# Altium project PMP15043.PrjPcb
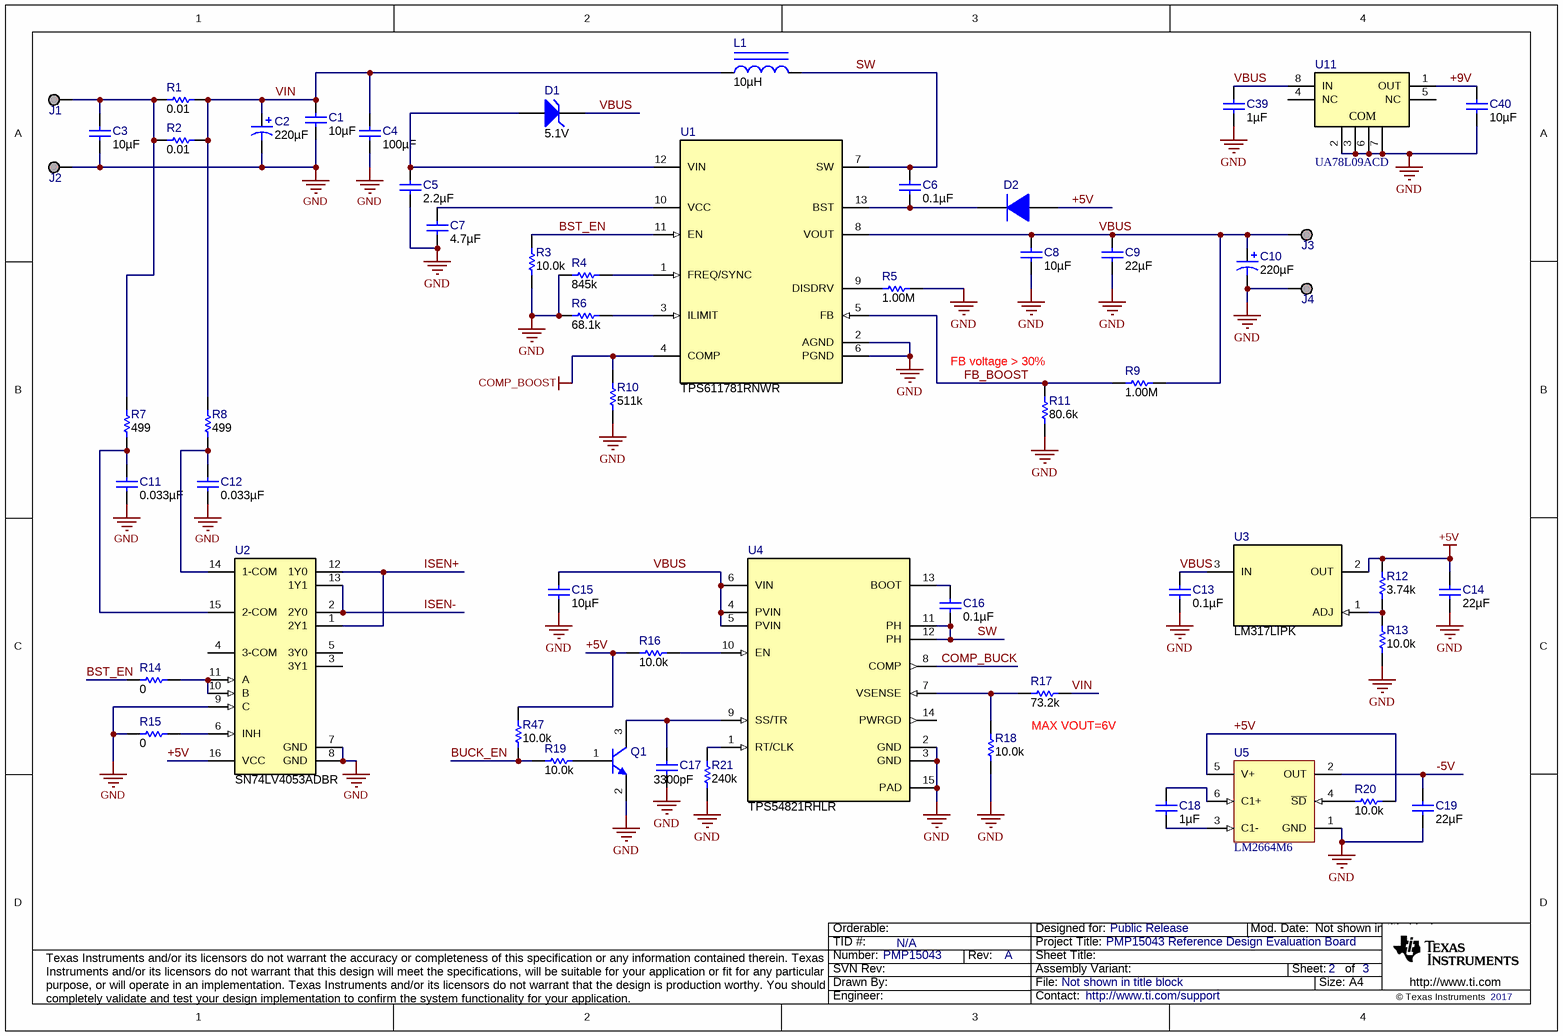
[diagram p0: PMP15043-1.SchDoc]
TID: N/A; TechSupport: http://www.ti.com/support; SCH_Rev: A; PRJ_Title: PMP15043 Reference Design Evaluation Board; PRJ_Number: PMP15043; PRJ_Customer: Public Release; PCB_Rev: A; CopyrightYear: 2017
2 sheets, 118 parts. Net scope: global (net labels, ports and power ports of the same name join across sheets).
Board file: PMP15043.PcbDoc
Sheets:
  PMP15043-1.SchDoc
  PMP15043-2.SchDoc

## Sheet PMP15043-1.SchDoc
size A4; Date: Not shown in title block; ApprovedBy: Not shown in title block; CheckedBy: Not shown in title block; Author: Not shown in title block; CompanyName: Not shown in title block; Engineer: Not shown in title block; Organization: Not shown in title block; Address1: Not shown in title block; Address2: Not shown in title block; Address3: Not shown in title block; Address4: Not shown in title block; DocumentNumber: 1; Revision: Use project parameter SCH_Rev; SheetNumber: 2; SheetTotal: 3; PageSetup: Record=PageOptions¦CenterHorizontal=True¦CenterVertical=True¦PrintScale=1.00¦XCorrection=1.00¦YCorrection=1.00¦PrintKind=0¦BorderSize=5000000¦LeftOffset=0¦BottomOffset=0¦Orientation=2¦PaperLength=1000¦PaperWidth=1000¦Scale=100¦PaperSource=15¦PrintQuality=600¦MediaType=1¦DitherType=10¦PaperKind=Letter¦PrintScaleMode=1

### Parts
C1  ValueDisplayed: 10µF  [0603]  (hidden comment: GRM188R61E106MA73D)
C2  ValueDisplayed: 220µF  [SM_RADIAL_G]  (hidden comment: EEE-FC1E221P)
C3  ValueDisplayed: 10µF  [0603]  (hidden comment: GRM188R61E106MA73D)
C4  ValueDisplayed: 100µF  [1210_270]  (hidden comment: GRM32ER61A107ME20L)
C5  ValueDisplayed: 2.2µF  [0402_070]  (hidden comment: GRM155R61E225KE11D)
C6  ValueDisplayed: 0.1µF  [0402]  (hidden comment: GRM155R61C104KA88D)
C7  ValueDisplayed: 4.7µF  [0402]  (hidden comment: GRM155R61A475MEAAD)
C8  ValueDisplayed: 10µF  [0603]  (hidden comment: GRM188R61E106MA73D)
C9  ValueDisplayed: 22µF  [1210_270]  (hidden comment: GRM32ER61E226KE15L)
C10  ValueDisplayed: 220µF  [SM_RADIAL_G]  (hidden comment: EEE-FC1E221P)
C11  ValueDisplayed: 0.033µF  [0402]  (hidden comment: GRM155R71A333KA01D)
C12  ValueDisplayed: 0.033µF  [0402]  (hidden comment: GRM155R71A333KA01D)
C13  ValueDisplayed: 0.1µF  [0402]  (hidden comment: GRM155R71E104KE14D)
C14  ValueDisplayed: 22µF  [0603]  (hidden comment: GRM188R61A226ME15D)
C15  ValueDisplayed: 10µF  [0603]  (hidden comment: GRM188R61E106MA73D)
C16  ValueDisplayed: 0.1µF  [0402]  (hidden comment: GRM155R61C104KA88D)
C17  ValueDisplayed: 3300pF  [0402]  (hidden comment: GRM155R71H332KA01D)
C18  ValueDisplayed: 1µF  [0603]  (hidden comment: GRM188R61A105KA61D)
C19  ValueDisplayed: 22µF  [0603]  (hidden comment: GRM188R61A226ME15D)
C39  ValueDisplayed: 1µF  [0603]  (hidden comment: GRM188R61E105KA12D)
C40  ValueDisplayed: 10µF  [0603]  (hidden comment: GRM188R61E106MA73D)
D1  value 5.1V  [SOD-323]  (hidden comment: BZT52C5V1S-7-F)
D2  1N4148X-TP  [SOD-523]  (value not drawn)
J1  Suggest using a net name here  [Keystone1502-2]  (value not drawn)
J2  Suggest using a net name here  [Keystone1502-2]  (value not drawn)
J3  Suggest using a net name here  [Keystone1502-2]  (value not drawn)
J4  Suggest using a net name here  [Keystone1502-2]  (value not drawn)
L1  ValueDisplayed: 10µH  [WE-HCC_1210]  (hidden comment: 7443321000)
Q1  MMBT3904-7-F  [SOT-23]  (value not drawn)
R1  ValueDisplayed: 0.01  [2010]  (hidden comment: CSRN2010FK10L0)
R2  ValueDisplayed: 0.01  [2010]  (hidden comment: CSRN2010FK10L0)
R3  ValueDisplayed: 10.0k  [0402]  (hidden comment: CRCW040210K0FKED)
R4  ValueDisplayed: 845k  [0402]  (hidden comment: CRCW0402845KFKED)
R5  ValueDisplayed: 1.00M  [0402]  (hidden comment: CRCW04021M00FKED)
R6  ValueDisplayed: 68.1k  [0402]  (hidden comment: CRCW040268K1FKED)
R7  ValueDisplayed: 499  [0603]  (hidden comment: CRCW0603499RFKEA)
R8  ValueDisplayed: 499  [0603]  (hidden comment: CRCW0603499RFKEA)
R9  ValueDisplayed: 1.00M  [0402]  (hidden comment: CRCW04021M00FKED)
R10  ValueDisplayed: 511k  [0402]  (hidden comment: CRCW0402511KFKED)
R11  ValueDisplayed: 80.6k  [0402]  (hidden comment: CRCW040280K6FKED)
R12  ValueDisplayed: 3.74k  [0402]  (hidden comment: CRCW04023K74FKED)
R13  ValueDisplayed: 10.0k  [0402]  (hidden comment: CRCW040210K0FKED)
R14  ValueDisplayed: 0  [0603]  (hidden comment: CRCW06030000Z0EA)
R15  ValueDisplayed: 0  [0603]  (hidden comment: CRCW06030000Z0EA)
R16  ValueDisplayed: 10.0k  [0402]  (hidden comment: CRCW040210K0FKED)
R17  ValueDisplayed: 73.2k  [0402]  (hidden comment: CRCW040273K2FKED)
R18  ValueDisplayed: 10.0k  [0402]  (hidden comment: CRCW040210K0FKED)
R19  ValueDisplayed: 10.0k  [0402]  (hidden comment: CRCW040210K0FKED)
R20  ValueDisplayed: 10.0k  [0402]  (hidden comment: CRCW040210K0FKED)
R21  ValueDisplayed: 240k  [0402]  (hidden comment: CRCW0402240KFKED)
R47  ValueDisplayed: 10.0k  [0402]  (hidden comment: CRCW040210K0FKED)
U1  TPS611781RNWR  [RNW0013A]
U2  SN74LV4053ADBR  [DB0016A_N]
U3  LM317LIPK  [PK0003A_N]
U4  TPS54821RHLR  [RHL0014A]
U5  LM2664M6  [MF06A_N]
U11  UA78L09ACD  [D0008A_N]

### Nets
+5V: C14.1 D2.2(A) R12.2 R16.1 R20.2 R47.2 U2.16(VCC) U3.2(OUT) U5.5(V+)
-5V: C19.1 U5.2(OUT)
COMP_BOOST: R10.2 U1.4(COMP)
GND: C1.2 C2.2(-) C3.2 C4.2 C5.1 C7.2 C8.2 C9.2 C10.2(-) C11.2 C12.2 C13.2 C14.2 C15.2 C17.2 C19.2 C39.2 C40.2 J2.1 J4.1 Q1.2(E) R3.1 R4.1 R5.2 R6.1 R10.1 R11.1 R13.1 R15.1 R18.1 R21.1 U1.2(AGND) U1.6(PGND) U2.7(GND) U2.8(GND) U2.9(C) U4.2(GND) U4.3(GND) U4.15(PAD) U5.1(GND) U11.2(GND) U11.3(GND) U11.6(GND) U11.7(GND)
+9V: C40.1 U11.1(OUT)
BST_EN: R3.2 R14.1 U1.11(EN)
BUCK_EN: R19.1 R47.1
COMP_BUCK: U4.8(COMP)
FB_BOOST: R9.1 R11.2 U1.5(FB)
ISEN+: U2.1(2Y1) U2.12(1Y0)
ISEN-: U2.2(2Y0) U2.13(1Y1)
SW: C6.1 C16.2 L1.2 U1.7(SW) U4.11(PH) U4.12(PH)
VBUS: C8.1 C9.1 C10.1(+) C13.1 C15.1 C39.1 D1.1(K) J3.1 R9.2 U1.8(VOUT) U3.3(IN) U4.4(PVIN) U4.5(PVIN) U4.6(VIN) U11.8(IN)
VIN: C1.1 C2.1(+) C4.1 L1.1 R1.2 R2.2 R8.2 R17.1
NetC3_1: C3.1 J1.1 R1.1 R2.1 R7.2
NetC5_2: C5.2 D1.2(A) U1.12(VIN)
NetC6_2: C6.2 D2.1(K) U1.13(BST)
NetC7_1: C7.1 U1.10(VCC)
NetC11_1: C11.1 R7.1 U2.15(2-COM)
NetC12_1: C12.1 R8.1 U2.14(1-COM)
NetC16_1: C16.1 U4.13(BOOT)
NetC17_1: C17.1 Q1.3(C) U4.9(SS/TR)
NetC18_1: C18.1 U5.6(C1+)
NetC18_2: C18.2 U5.3(C1-)
NetQ1_1: Q1.1(B) R19.2
NetR4_2: R4.2 U1.1(FREQ/SYNC)
NetR5_1: R5.1 U1.9(DISDRV)
NetR6_2: R6.2 U1.3(ILIMIT)
NetR12_1: R12.1 R13.2 U3.1(ADJ)
NetR14_2: R14.2 U2.10(B) U2.11(A)
NetR15_2: R15.2 U2.6(INH)
NetR16_2: R16.2 U4.10(EN)
NetR17_2: R17.2 R18.2 U4.7(VSENSE)
NetR20_1: R20.1 U5.4(~{SD})
NetR21_2: R21.2 U4.1(RT/CLK)

Not connected (* = marked no-connect by the designer): U2 3(3Y1) 4(3-COM) 5(3Y0); U4 14(PWRGD); U11 4(NC) 5(NC)

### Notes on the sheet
- (near R11) FB voltage > 30%
- MAX VOUT=6V

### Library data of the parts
C1 C3 C8 C15 = GRM188R61E106MA73D: CAP, CERM, 10 µF, 25 V, +/- 20%, X5R, 0603; Manufacturer: MuRata; Polarized: N; CompType: Capacitor; Value: 10uF; U/M: EA; Cap_F: 0.00001; Tolerance_%: 20; Value1: Unknown; VDC_V: 25; Value2: 25V; TaMin_C: -55; TaMax_C: 85; AEC Category: Q200
C2 C10 = EEE-FC1E221P: CAP, AL, 220 µF, 25 V, +/- 20%, 0.15 ohm, SMD; Manufacturer: Panasonic; Polarized: Y; CompType: Capacitor; Value: 220uF; U/M: EA; Cap_F: 0.00022; Tolerance_%: 20; VDC_V: 25; Value2: 25V; ESR_ohm: 0.15; IRMS_A: 0.67; TaMin_C: -40; TaMax_C: 105; Cap_Case: G; SizeAreaWB_mm2: 172.2; SizeArea_mm2: 123.6; SizeX_mm: 12; SizeY_mm: 10.3; SizeZ_mm: 10.2; AEC Category: Q200
C4 = GRM32ER61A107ME20L: CAP, CERM, 100 µF, 10 V,+/- 20%, X5R, 1210; Manufacturer: MuRata; Polarized: N; CompType: Capacitor; Value: 100uF; U/M: EA; Cap_F: 0.0001; Tolerance_%: 20; Value1: Unknown; VDC_V: 10; Value2: 10V; TaMin_C: -55; TaMax_C: 85; Cap_Case: 1210; SizeArea_mm2: 8; SizeAreaWB_mm2: 14.7; SizeX_mm: 3.2; SizeY_mm: 2.5; SizeZ_mm: 2.7; AEC Category: Q200
C5 = GRM155R61E225KE11D: CAP, CERM, 2.2 µF, 25 V,+/- 10%, X5R, 0402; Manufacturer: MuRata; Polarized: N; CompType: Capacitor; Value: 2.2uF; U/M: EA; Cap_F: 0.0000022; Tolerance_%: 10; Value1: Unknown; VDC_V: 25; Value2: 25V; TaMin_C: -55; TaMax_C: 85; Cap_Case: 0402; AEC Category: Q200; SizeArea_mm2: 0.5; SizeAreaWB_mm2: 3; SizeX_mm: 1; SizeZ_mm: 0.7; Green_Lifecycle: Active; Green_REACh: Passed
C6 C16 = GRM155R61C104KA88D: CAP, CERM, 0.1 µF, 16 V, +/- 10%, X5R, 0402; Manufacturer: MuRata; Polarized: N; CompType: Capacitor; Value: 0.1uF; U/M: EA; Cap_F: 0.0000001; Tolerance_%: 10; Value1: Unknown; VDC_V: 16; Value2: 16V; TaMin_C: -55; TaMax_C: 85; AEC Category: Q200
C7 = GRM155R61A475MEAAD: CAP, CERM, 4.7 µF, 10 V, +/- 20%, X5R, 0402; Manufacturer: MuRata; Polarized: N; CompType: Capacitor; Value: 4.7uF; U/M: EA; Cap_F: 0.0000047; Tolerance_%: 20; Value1: Unknown; VDC_V: 10; Value2: 10V; TaMin_C: -55; TaMax_C: 85; SizeArea_mm2: 0.5; SizeAreaWB_mm2: 3; SizeX_mm: 1; SizeZ_mm: 0.6; AEC Category: Q200
C9 = GRM32ER61E226KE15L: CAP, CERM, 22 µF, 25 V, +/- 10%, X5R, 1210; Manufacturer: MuRata; Polarized: N; CompType: Capacitor; Value: 22uF; U/M: EA; Cap_F: 0.000022; Tolerance_%: 10; ESR_ohm: 0.002; Value1: 0.002 ohm; VDC_V: 25; Value2: 25V; IRMS_A: 3.67; TaMin_C: -55; TaMax_C: 85; Cap_Case: 1210; SizeArea_mm2: 8; SizeAreaWB_mm2: 14.7; SizeX_mm: 3.2; SizeY_mm: 2.5; SizeZ_mm: 2.7; AEC Category: Q200
C11 C12 = GRM155R71A333KA01D: CAP, CERM, 0.033 µF, 10 V,+/- 10%, X7R, 0402; Manufacturer: MuRata; Polarized: N; CompType: Capacitor; Value: 0.033uF; U/M: EA; Cap_F: 0.000000033; Tolerance_%: 10; Value1: Unknown; Value2: 10V; TaMin_C: -55; TaMax_C: 125; SizeArea_mm2: 0.5; SizeAreaWB_mm2: 3; SizeX_mm: 1; SizeZ_mm: 0.6; AEC Category: Q200; Green_Lifecycle: Active; Green_REACh: Passed
C13 = GRM155R71E104KE14D: CAP, CERM, 0.1 µF, 25 V,+/- 10%, X7R, 0402; Manufacturer: MuRata; Polarized: N; CompType: Capacitor; Value: 0.1uF; U/M: EA; Cap_F: 0.0000001; Tolerance_%: 10; Value1: Unknown; VDC_V: 25; Value2: 25V; TaMin_C: -55; TaMax_C: 125; SizeArea_mm2: 0.5; SizeAreaWB_mm2: 3; SizeX_mm: 1; SizeZ_mm: 0.6; AEC Category: Q200; Green_Lifecycle: Active; Green_REACh: Passed
C14 C19 = GRM188R61A226ME15D: CAP, CERM, 22 µF, 10 V,+/- 20%, X5R, 0603; Manufacturer: MuRata; Polarized: N; CompType: Capacitor; Value: 22uF; U/M: EA; Cap_F: 0.000022; Tolerance_%: 20; VDC_V: 10; Value2: 10V; TaMin_C: -55; TaMax_C: 85; SizeArea_mm2: 1.28; SizeAreaWB_mm2: 4.68; SizeX_mm: 1.6; SizeY_mm: 0.8; SizeZ_mm: 1; AEC Category: Q200; Green_Lifecycle: Active; Green_REACh: Passed
C17 = GRM155R71H332KA01D: CAP, CERM, 3300 pF, 50 V,+/- 10%, X7R, 0402; Manufacturer: MuRata; Polarized: N; CompType: Capacitor; Value: 3300pF; U/M: EA; Cap_F: 0.0000000033; Tolerance_%: 10; Value1: Unknown; VDC_V: 50; Value2: 50V; TaMin_C: -55; TaMax_C: 125; SizeArea_mm2: 0.5; SizeAreaWB_mm2: 3; SizeX_mm: 1; SizeZ_mm: 0.6; AEC Category: Q200; Green_Lifecycle: Active; Green_REACh: Passed
C18 = GRM188R61A105KA61D: CAP, CERM, 1 µF, 10 V,+/- 10%, X5R, 0603; Manufacturer: MuRata; Polarized: N; CompType: Capacitor; Value: 1uF; U/M: EA; Cap_F: 0.000001; Tolerance_%: 10; Value1: Unknown; Value2: 10V; TaMin_C: -55; TaMax_C: 85; SizeArea_mm2: 1.28; SizeAreaWB_mm2: 4.68; SizeX_mm: 1.6; SizeY_mm: 0.8; SizeZ_mm: 1; AEC Category: Q200; Green_Lifecycle: Active; Green_REACh: Passed
C39 = GRM188R61E105KA12D: CAP, CERM, 1 µF, 25 V,+/- 10%, X5R, 0603; Manufacturer: MuRata; Polarized: N; CompType: Capacitor; Value: 1uF; U/M: EA; Cap_F: 0.000001; Tolerance_%: 10; Value1: Unknown; VDC_V: 25; Value2: 25V; TaMin_C: -55; TaMax_C: 85; SizeArea_mm2: 1.28; SizeAreaWB_mm2: 4.68; SizeX_mm: 1.6; SizeY_mm: 0.8; SizeZ_mm: 1; AEC Category: Q200; Green_Lifecycle: Active; Green_REACh: Passed
C40 = GRM188R61E106MA73D: CAP, CERM, 10 µF, 25 V,+/- 20%, X5R, 0603; Manufacturer: MuRata; Polarized: N; CompType: Capacitor; Value: 10uF; U/M: EA; Cap_F: 0.00001; Tolerance_%: 20; VDC_V: 25; Value2: 25V; TaMin_C: -55; TaMax_C: 85; SizeArea_mm2: 1.28; SizeAreaWB_mm2: 4.68; SizeX_mm: 1.6; SizeY_mm: 0.8; SizeZ_mm: 1; AEC Category: Q200; Green_Lifecycle: Active; Green_REACh: Passed
D1 = BZT52C5V1S-7-F: Diode, Zener, 5.1 V, 200 mW, SOD-323; Manufacturer: Diodes Inc.; SymbolCreator: a0412235; U/M: EA; Power_W: 0.2; Vz_V: 5.1; Value1: 0.2W; RJA_CperW: 625; SizeAreaWB_mm2: 8.695; SizeArea_mm2: 3.645; SizeX_mm: 2.7; SizeY_mm: 1.35; SizeZ_mm: 1; AEC Category: Q101; Green_Lifecycle: Active; Green_REACh: Passed
D2 = 1N4148X-TP: Diode, Switching, 75 V, 0.3 A, SOD-523; Manufacturer: Micro Commercial Components; U/M: EA; Vf_V: 1.25; Value: 75V; Value1: 0.3A; Value2: 1.25V; Io_A: 0.3; Vr_V: 75; TJmax_C: 150; SizeAreaWB_mm2: 5.13; SizeArea_mm2: 1.53; SizeX_mm: 1.7; SizeY_mm: 0.9; SizeZ_mm: 0.65; AEC Category: Q101; Green_Lifecycle: Not Set; Green_REACh: Incomplete
J1-J4 = 1502-2: Terminal, Turret, TH, Double; Manufacturer: Keystone; CompType: Turret Terminal; U/M: EA
L1 = 7443321000: Inductor, Shielded Drum Core, Ferrite, 10 µH, 9 A, 0.0144 ohm, SMD; Manufacturer: Wurth Elektronik; Value: 10uH; Ind_H: 10.0E-6; Imax_A: 9; Irms: 9A @ 50C rise; Isat: 10A @ 30% inductance drop; DCR_ohm: 0.0144; Value2: 9A; SizeAreaWB_mm2: 188.94; SizeArea_mm2: 137.94; SizeX_mm: 12.1; SizeY_mm: 11.4; SizeZ_mm: 10; AEC Category: Q200; Green_Lifecycle: Active; Green_REACh: Passed
Q1 = MMBT3904-7-F, Diodes Inc.: Transistor, NPN, 40 V, 0.2 A, SOT-23; CompType: BJT; PNP: 0; NPN: 1; Vceo_V: 40; Vcesat1_V: 0.2; Value: 40 V; Value1: 0.2 A; HfeMax: 400; TaMin_C: -55; TaMax_C: 150; SizeAreaWB_mm2: 14; SizeArea_mm2: 7.5; SizeX_mm: 2.5; SizeY_mm: 3; SizeZ_mm: 1.1; U/M: EA; AEC Category: Q101
R1 R2 = CSRN2010FK10L0: RES, 0.01, 1%, 1 W, 2010; Manufacturer: Stackpole Electronics Inc; CompType: Resistor; Value: 0.01; Value_Code: R010; Tolerance_%: 1; Value2: 1W; TempCo: 250 ppm/C; SizeArea_mm2: 12.5; SizeX_mm: 5; SizeY_mm: 2.5; SizeZ_mm: 1.66; EIA_Code: E96; U/M: EA; AEC Category: Q200
R3 R13 R16 R18-R20 R47 = CRCW040210K0FKED: RES, 10.0 k, 1%, 0.063 W, 0402; Manufacturer: Vishay-Dale; CompType: Resistor; Value: 10.0k; Res_ohm: 10000; Value_Code: 10k0; Tolerance_%: 1; Power_W: 0.063; Value2: 0.063W; VDC_V: 50; TempCo: 100 ppm/C; SizeArea_mm2: 0.5; SizeZ_mm: 0.6; EIA_Code: E96; U/M: EA; AEC Category: Q200
R4 = CRCW0402845KFKED: RES, 845 k, 1%, 0.063 W, 0402; Manufacturer: Vishay-Dale; CompType: Resistor; Value: 845k; Res_ohm: 845000; Tolerance_%: 1; Power_W: 0.063; Value2: 0.063W; VDC_V: 50; TempCo: 100 ppm/C; SizeArea_mm2: 0.5; SizeZ_mm: 0.6; EIA_Code: E96; U/M: EA; AEC Category: Q200
R5 R9 = CRCW04021M00FKED: RES, 1.00 M, 1%, 0.063 W, 0402; Manufacturer: Vishay-Dale; CompType: Resistor; Value: 1.00Meg; Res_ohm: 1000000; Value_Code: 1M00; Tolerance_%: 1; Power_W: 0.063; Value2: 0.063W; VDC_V: 50; TempCo: 100 ppm/C; SizeArea_mm2: 0.5; SizeZ_mm: 0.6; EIA_Code: E96; U/M: EA; AEC Category: Q200
R6 = CRCW040268K1FKED: RES, 68.1 k, 1%, 0.063 W, 0402; Manufacturer: Vishay-Dale; CompType: Resistor; Value: 68.1k; Res_ohm: 68100; Value_Code: 68k1; Tolerance_%: 1; Power_W: 0.063; Value2: 0.063W; VDC_V: 50; TempCo: 100 ppm/C; SizeArea_mm2: 0.5; SizeZ_mm: 0.6; EIA_Code: E96; U/M: EA; AEC Category: Q200; Green_Lifecycle: Active; Green_REACh: Passed
R7 R8 = CRCW0603499RFKEA: RES, 499, 1%, 0.1 W, 0603; Manufacturer: Vishay-Dale; CompType: Resistor; Value: 499; Value_Code: 499R; Tolerance_%: 1; Power_W: 0.1; Value2: 0.1W; VDC_V: 75; TempCo: 100 ppm/C; SizeArea_mm2: 1.28; SizeX_mm: 1.6; SizeY_mm: 0.8; EIA_Code: E96; U/M: EA; AEC Category: Q200; Green_Lifecycle: Active; Green_REACh: Passed
R10 = CRCW0402511KFKED: RES, 511 k, 1%, 0.063 W, 0402; Manufacturer: Vishay-Dale; CompType: Resistor; Value: 511k; Res_ohm: 511000; Tolerance_%: 1; Power_W: 0.063; Value2: 0.063W; VDC_V: 50; TempCo: 100 ppm/C; SizeArea_mm2: 0.5; SizeZ_mm: 0.6; EIA_Code: E96; U/M: EA; AEC Category: Q200
R11 = CRCW040280K6FKED: RES, 80.6 k, 1%, 0.063 W, 0402; Manufacturer: Vishay-Dale; CompType: Resistor; Value: 80.6k; Res_ohm: 80600; Value_Code: 80k6; Tolerance_%: 1; Power_W: 0.063; Value2: 0.063W; VDC_V: 50; TempCo: 100 ppm/C; SizeArea_mm2: 0.5; SizeZ_mm: 0.6; EIA_Code: E96; U/M: EA; AEC Category: Q200
R12 = CRCW04023K74FKED: RES, 3.74 k, 1%, 0.063 W, 0402; Manufacturer: Vishay-Dale; CompType: Resistor; Value: 3.74k; Res_ohm: 3740; Value_Code: 3k74; Tolerance_%: 1; Power_W: 0.063; Value2: 0.063W; VDC_V: 50; TempCo: 100 ppm/C; SizeArea_mm2: 0.5; SizeZ_mm: 0.6; EIA_Code: E96; U/M: EA; AEC Category: Q200
R14 R15 = CRCW06030000Z0EA: RES, 0, 5%, 0.1 W, 0603; Manufacturer: Vishay-Dale; CompType: Resistor; Value: 0; Value_Code: 0000; Tolerance_%: 5; Power_W: 0.1; Value2: 0.1W; VDC_V: 75; TempCo: 200 ppm/C; SizeArea_mm2: 1.28; SizeX_mm: 1.6; SizeY_mm: 0.8; SizeZ_mm: 1; EIA_Code: E24; U/M: EA; AEC Category: Q200; Green_Lifecycle: Active; Green_REACh: Passed
R17 = CRCW040273K2FKED: RES, 73.2 k, 1%, 0.063 W, 0402; Manufacturer: Vishay-Dale; CompType: Resistor; Value: 73.2k; Res_ohm: 73200; Value_Code: 73k2; Tolerance_%: 1; Power_W: 0.063; Value2: 0.063W; VDC_V: 50; TempCo: 100 ppm/C; SizeArea_mm2: 0.5; SizeZ_mm: 0.6; EIA_Code: E96; U/M: EA; AEC Category: Q200; Green_Lifecycle: Active; Green_REACh: Passed
R21 = CRCW0402240KFKED: RES, 240 k, 1%, 0.063 W, 0402; Manufacturer: Vishay-Dale; CompType: Resistor; Value: 240k; Res_ohm: 240000; Tolerance_%: 1; Power_W: 0.063; Value2: 0.063W; VDC_V: 50; TempCo: 100 ppm/C; SizeArea_mm2: 0.5; SizeZ_mm: 0.6; U/M: EA; AEC Category: Q200; Green_Lifecycle: Active; Green_REACh: Passed
U1 = TPS611781RNWR: 20-V, 10-A Fully-Integrated Synchronous Boost with Load Disconnect, RNW0013A (VQFN-HR-13); Alternate PartNumber: TPS611781RNWT; Manufacturer: Texas Instruments; SymbolCreator: Altium; CompType: IC; U/M: EA; SizeArea_mm2: 10.5; SizeAreaWB_mm2: 18; SizeX_mm: 3.5; SizeY_mm: 3; SizeZ_mm: 1
U2 = SN74LV4053ADBR: Triple 2-Channel Analog Multiplexer/Demultiplexer, DB0016A, LARGE T&R; Manufacturer: Texas Instruments; Alternate PartNumber: Equivalent; VCC(Min)(V): 2; VCC(Max)(V): 5.5; Configuration: 3 X SPDT; Bandwidth(Max)(MHz): 50; Ron(Max)(Ohms): 75; Ron(Typ)(Ohms): 23; Crosstalk: Yes; Rating: Catalog; Output Type: CMOS
U3 = LM317LIPK: 3/8 Pin 100mA Adjustable Positive Regulator, PK0003A (SOT-3); Manufacturer: Texas Instruments; SymbolCreater: a0411947; SizeArea_mm2: 18.45; SizeAreaWB_mm2: 28.05; SizeX_mm: 4.1; SizeY_mm: 4.5; SizeZ_mm: 1.6; CompType: IC; U/M: EA
U4 = TPS54821RHLR: 4.5V to 17V Input, 8-A Synchronous Step-Down Converter with Hiccup Current Limit, RHL0014A (VQFN-14); Alternate PartNumber: TPS54821RHLT; Manufacturer: Texas Instruments; SymbolCreator: Altium; SizeArea_mm2: 13.3225; SizeAreaWB_mm2: 21.6225; SizeX_mm: 3.65; SizeZ_mm: 1; CompType: IC; U/M: EA; Green_Lifecycle: Active; Green_REACh: Passed
U5 = LM2664M6: Switched Capacitor Voltage Converter, 6-pin SOT-23; Manufacturer: Texas Instruments; PackageTopMarking: S03A*XTT; PowerWise: N; CompType: Switch Caps
U11 = UA78L09ACD: Fixed Regulator with 11.5 to 24 V Input and 9 V Output, 0 to 125 degC, 8-Pin SOIC (D), Green (RoHS & no Sb/Br); Manufacturer: Texas Instruments; Alternate PartNumber: Equivalent; Iout(Max)(A): 0.1; Iq(Typ)(mA): 6; Vin(Max)(V): 24; Vin(Min)(V): 11.5; Vout(Max)(V): 9; Vdo(Typ)(V): 1.7

## Sheet PMP15043-2.SchDoc
size A4; Date: Not shown in title block; ApprovedBy: Not shown in title block; CheckedBy: Not shown in title block; Author: Not shown in title block; CompanyName: Not shown in title block; Engineer: Not shown in title block; Organization: Not shown in title block; Address1: Not shown in title block; Address2: Not shown in title block; Address3: Not shown in title block; Address4: Not shown in title block; DocumentNumber: 1; Revision: Use project parameter SCH_Rev; SheetNumber: 3; SheetTotal: 3; PageSetup: Record=PageOptions¦CenterHorizontal=True¦CenterVertical=True¦PrintScale=0.94¦XCorrection=1.00¦YCorrection=1.00¦PrintKind=0¦BorderSize=5000000¦LeftOffset=0¦BottomOffset=0¦Orientation=2¦PaperLength=1000¦PaperWidth=1000¦Scale=100¦PaperSource=15¦PrintQuality=600¦MediaType=1¦DitherType=10¦PrintScaleMode=1¦PaperKind=Letter
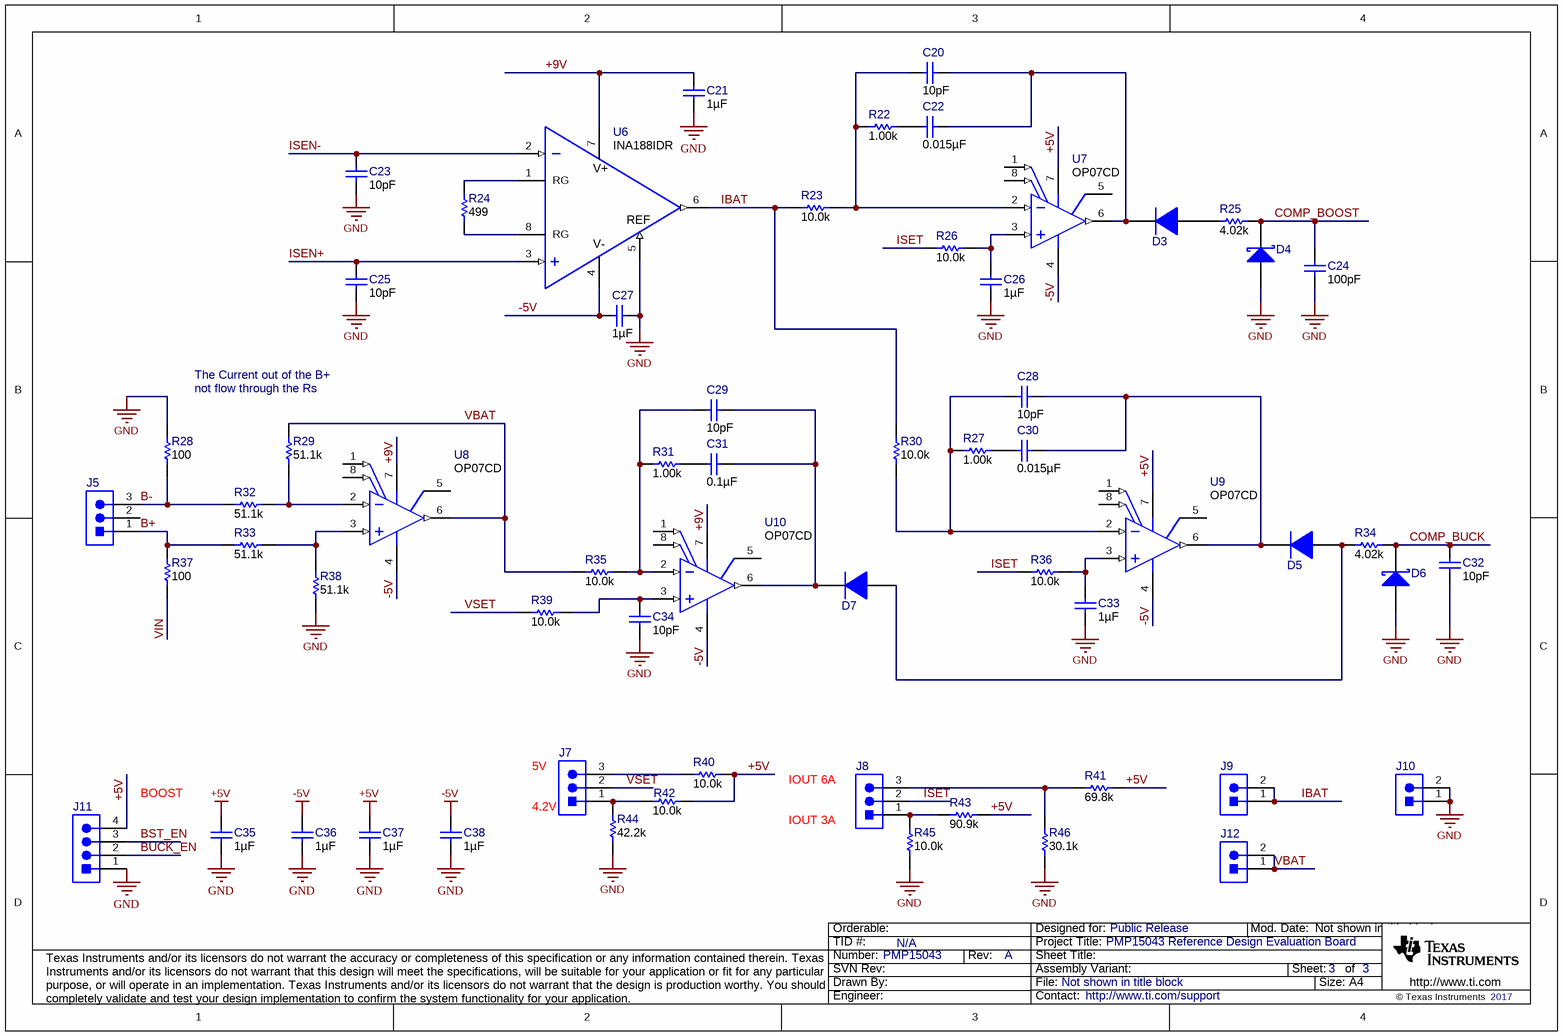
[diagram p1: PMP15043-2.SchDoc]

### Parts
C20  ValueDisplayed: 10pF  [0402]  (hidden comment: GRM1555C1H100JA01D)
C21  ValueDisplayed: 1µF  [0402]  (hidden comment: GRM155R61A105KE15D)
C22  ValueDisplayed: 0.015µF  [0402]  (hidden comment: GRM155R71C153JA01D)
C23  ValueDisplayed: 10pF  [0402]  (hidden comment: GRM1555C1H100JA01D)
C24  ValueDisplayed: 100pF  [0402]  (hidden comment: GRM1555C1H101JA01D)
C25  ValueDisplayed: 10pF  [0402]  (hidden comment: GRM1555C1H100JA01D)
C26  ValueDisplayed: 1µF  [0402]  (hidden comment: GRM155R70J105KA12D)
C27  ValueDisplayed: 1µF  [0402]  (hidden comment: GRM155R61A105KE15D)
C28  ValueDisplayed: 10pF  [0402]  (hidden comment: GRM1555C1H100JA01D)
C29  ValueDisplayed: 10pF  [0402]  (hidden comment: GRM1555C1H100JA01D)
C30  ValueDisplayed: 0.015µF  [0402]  (hidden comment: GRM155R71C153JA01D)
C31  ValueDisplayed: 0.1µF  [0402]  (hidden comment: GRM155R61C104KA88D)
C32  ValueDisplayed: 10pF  [0402]  (hidden comment: GRM1555C1H100JA01D)
C33  ValueDisplayed: 1µF  [0402]  (hidden comment: GRM155R70J105KA12D)
C34  ValueDisplayed: 10pF  [0402]  (hidden comment: GRM1555C1H100JA01D)
C35  ValueDisplayed: 1µF  [0402]  (hidden comment: GRM155R61A105KE15D)
C36  ValueDisplayed: 1µF  [0402]  (hidden comment: GRM155R61A105KE15D)
C37  ValueDisplayed: 1µF  [0402]  (hidden comment: GRM155R61A105KE15D)
C38  ValueDisplayed: 1µF  [0402]  (hidden comment: GRM155R61A105KE15D)
D3  1N4148X-TP  [SOD-523]  (value not drawn)
D4  BAT54WS-7-F  [SOD-323]  (value not drawn)
D5  1N4148X-TP  [SOD-523]  (value not drawn)
D6  BAT54WS-7-F  [SOD-323]  (value not drawn)
D7  1N4148X-TP  [SOD-523]  (value not drawn)
J5  TSW-103-07-G-S  [TSW-103-07-G-S]  (value not drawn)
J7  TSW-103-07-G-S  [TSW-103-07-G-S]  (value not drawn)
J8  TSW-103-07-G-S  [TSW-103-07-G-S]  (value not drawn)
J9  TSW-102-07-G-S  [TSW-102-07-G-S]  (value not drawn)
J10  TSW-102-07-G-S  [TSW-102-07-G-S]  (value not drawn)
J11  TSW-104-07-G-S  [TSW-104-07-G-S]  (value not drawn)
J12  TSW-102-07-G-S  [TSW-102-07-G-S]  (value not drawn)
R22  ValueDisplayed: 1.00k  [0402]  (hidden comment: CRCW04021K00FKED)
R23  ValueDisplayed: 10.0k  [0402]  (hidden comment: CRCW040210K0FKED)
R24  ValueDisplayed: 499  [0603]  (hidden comment: RC0603FR-07499RL)
R25  ValueDisplayed: 4.02k  [0402]  (hidden comment: CRCW04024K02FKED)
R26  ValueDisplayed: 10.0k  [0402]  (hidden comment: CRCW040210K0FKED)
R27  ValueDisplayed: 1.00k  [0402]  (hidden comment: CRCW04021K00FKED)
R28  ValueDisplayed: 100  [0402]  (hidden comment: CRCW0402100RFKED)
R29  ValueDisplayed: 51.1k  [0402]  (hidden comment: CRCW040251K1FKED)
R30  ValueDisplayed: 10.0k  [0402]  (hidden comment: CRCW040210K0FKED)
R31  ValueDisplayed: 1.00k  [0402]  (hidden comment: CRCW04021K00FKED)
R32  ValueDisplayed: 51.1k  [0402]  (hidden comment: CRCW040251K1FKED)
R33  ValueDisplayed: 51.1k  [0402]  (hidden comment: CRCW040251K1FKED)
R34  ValueDisplayed: 4.02k  [0402]  (hidden comment: CRCW04024K02FKED)
R35  ValueDisplayed: 10.0k  [0402]  (hidden comment: CRCW040210K0FKED)
R36  ValueDisplayed: 10.0k  [0402]  (hidden comment: CRCW040210K0FKED)
R37  ValueDisplayed: 100  [0402]  (hidden comment: CRCW0402100RFKED)
R38  ValueDisplayed: 51.1k  [0402]  (hidden comment: CRCW040251K1FKED)
R39  ValueDisplayed: 10.0k  [0402]  (hidden comment: CRCW040210K0FKED)
R40  ValueDisplayed: 10.0k  [0402]  (hidden comment: CRCW040210K0FKED)
R41  ValueDisplayed: 69.8k  [0402]  (hidden comment: CRCW040269K8FKED)
R42  ValueDisplayed: 10.0k  [0402]  (hidden comment: CRCW040210K0FKED)
R43  ValueDisplayed: 90.9k  [0402]  (hidden comment: CRCW040290K9FKED)
R44  ValueDisplayed: 42.2k  [0402]  (hidden comment: CRCW040242K2FKED)
R45  ValueDisplayed: 10.0k  [0402]  (hidden comment: CRCW040210K0FKED)
R46  ValueDisplayed: 30.1k  [0402]  (hidden comment: CRCW040230K1FKED)
U6  INA188IDR  [D0008A_N]
U7  OP07CD  [D0008A_N]
U8  OP07CD  [D0008A_N]
U9  OP07CD  [D0008A_N]
U10  OP07CD  [D0008A_N]

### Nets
+5V: C35.1 C37.1 J11.4 R40.2 R41.2 R42.2 R43.2 U7.7(VCC+) U9.7(VCC+)
-5V: C27.1 C36.1 C38.1 U6.4(V-) U7.4(VCC-) U8.4(VCC-) U9.4(VCC-) U10.4(VCC-)
COMP_BOOST: C24.1 D4.1(K) R25.1
GND: C21.2 C23.2 C24.2 C25.2 C26.2 C27.2 C32.2 C33.2 C34.2 C35.2 C36.2 C37.2 C38.2 D4.2(A) D6.2(A) J10.1 J10.2 J11.1 R28.2 R38.1 R44.1 R45.1 R46.1 U6.5(REF)
+9V: C21.1 U6.7(V+) U8.7(VCC+) U10.7(VCC+)
B+: J5.1 R33.1 R37.2
B-: J5.3 R28.1 R32.1
BST_EN: J11.3
BUCK_EN: J11.2
COMP_BUCK: C32.1 D6.1(K) R34.1
IBAT: J9.1 J9.2 R23.2 R30.1 U6.6(OUT)
ISEN+: C25.1 U6.3(IN+)
ISEN-: C23.1 U6.2(IN-)
ISET: J8.2 R26.2 R36.2
VBAT: J12.1 J12.2 R29.2 R35.1 U8.6(OUT)
VIN: R37.1
VSET: J7.2 R39.2
NetC20_1: C20.1 C22.1 D3.1(K) U7.6(OUT)
NetC20_2: C20.2 R22.1 R23.1 U7.2(IN-)
NetC22_2: C22.2 R22.2
NetC26_1: C26.1 R26.1 U7.3(IN+)
NetC28_1: C28.1 C30.1 D5.1(K) U9.6(OUT)
NetC28_2: C28.2 R27.1 R30.2 U9.2(IN-)
NetC29_1: C29.1 C31.1 D7.1(K) U10.6(OUT)
NetC29_2: C29.2 R31.1 R35.2 U10.2(IN-)
NetC30_2: C30.2 R27.2
NetC31_2: C31.2 R31.2
NetC33_1: C33.1 R36.1 U9.3(IN+)
NetC34_1: C34.1 R39.1 U10.3(IN+)
NetD3_2: D3.2(A) R25.2
NetD5_2: D5.2(A) D7.2(A) R34.2
NetJ7_1: J7.1 R42.1 R44.2
NetJ7_3: J7.3 R40.1
NetJ8_1: J8.1 R43.1 R45.2
NetJ8_3: J8.3 R41.1 R46.2
NetR24_1: R24.1 U6.8(RG)
NetR24_2: R24.2 U6.1(RG)
NetR29_1: R29.1 R32.2 U8.2(IN-)
NetR33_2: R33.2 R38.2 U8.3(IN+)

Not connected (* = marked no-connect by the designer): J5 2; U7 1(OFFSET_N1) 5(NC) 8(OFFSET_N2); U8 1(OFFSET_N1) 5(NC) 8(OFFSET_N2); U9 1(OFFSET_N1) 5(NC) 8(OFFSET_N2); U10 1(OFFSET_N1) 5(NC) 8(OFFSET_N2)

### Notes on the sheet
- The Current out of the B+
- not flow through the Rs
- (near J7) 5V
- IOUT 6A
- BOOST
- (near J7) 4.2V
- IOUT 3A

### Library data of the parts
C20 C23 C25 C28 C29 C32 C34 = GRM1555C1H100JA01D: CAP, CERM, 10 pF, 50 V,+/- 5%, C0G/NP0, 0402; Manufacturer: MuRata; Polarized: N; CompType: Capacitor; Value: 10pF; U/M: EA; Cap_F: 0.00000000001; Tolerance_%: 5; Value1: Unknown; VDC_V: 50; Value2: 50V; TaMin_C: -55; TaMax_C: 125; SizeArea_mm2: 0.5; SizeAreaWB_mm2: 3; SizeX_mm: 1; SizeZ_mm: 0.6; AEC Category: Q200; Green_Lifecycle: Active; Green_REACh: Passed
C21 C27 C35-C38 = GRM155R61A105KE15D: CAP, CERM, 1 µF, 10 V,+/- 10%, X5R, 0402; Manufacturer: MuRata; Polarized: N; CompType: Capacitor; Value: 1uF; U/M: EA; Cap_F: 0.000001; Tolerance_%: 10; Value1: Unknown; Value2: 10V; TaMin_C: -55; TaMax_C: 85; SizeArea_mm2: 0.5; SizeAreaWB_mm2: 3; SizeX_mm: 1; SizeZ_mm: 0.6; AEC Category: Q200; Green_Lifecycle: Active; Green_REACh: Passed
C22 C30 = GRM155R71C153JA01D: CAP, CERM, 0.015 µF, 16 V,+/- 5%, X7R, 0402; Manufacturer: MuRata; Polarized: N; CompType: Capacitor; Value: 0.015uF; U/M: EA; Cap_F: 0.000000015; Tolerance_%: 5; Value1: Unknown; VDC_V: 16; Value2: 16V; TaMin_C: -55; TaMax_C: 125; AEC Category: Q200; SizeArea_mm2: 0.5; SizeAreaWB_mm2: 3; SizeX_mm: 1; SizeZ_mm: 0.6
C24 = GRM1555C1H101JA01D: CAP, CERM, 100 pF, 50 V,+/- 5%, C0G/NP0, 0402; Manufacturer: MuRata; Polarized: N; CompType: Capacitor; Value: 100pF; U/M: EA; Cap_F: 0.0000000001; Tolerance_%: 5; Value1: Unknown; VDC_V: 50; Value2: 50V; TaMin_C: -55; TaMax_C: 125; SizeArea_mm2: 0.5; SizeAreaWB_mm2: 3; SizeX_mm: 1; SizeZ_mm: 0.6; AEC Category: Q200; Green_Lifecycle: Active; Green_REACh: Passed
C26 C33 = GRM155R70J105KA12D: CAP, CERM, 1 µF, 6.3 V,+/- 10%, X7R, 0402; Manufacturer: MuRata; Polarized: N; CompType: Capacitor; Value: 1uF; U/M: EA; Cap_F: 0.000001; Tolerance_%: 10; Value1: Unknown; VDC_V: 6.3; Value2: 6.3V; TaMin_C: -55; TaMax_C: 125; SizeArea_mm2: 0.5; SizeAreaWB_mm2: 3; SizeX_mm: 1; SizeZ_mm: 0.6; AEC Category: Q200
C31 = GRM155R61C104KA88D: as C6 on sheet PMP15043-1
D3 D5 D7 = 1N4148X-TP: as D2 on sheet PMP15043-1
D4 D6 = BAT54WS-7-F: Diode, Schottky, 30 V, 0.2 A, SOD-323; Manufacturer: Diodes Inc.; U/M: EA; Vf_V: 0.7; Value: 30V; Value1: 0.2A; Value2: 0.7V; Io_A: 0.2; Vr_V: 30; TJmax_C: 125; SizeAreaWB_mm2: 8.695; SizeArea_mm2: 3.645; SizeX_mm: 2.7; SizeY_mm: 1.35; SizeZ_mm: 1; AEC Category: Q101; Green_Lifecycle: Active; Green_REACh: Passed
J5 J7 J8 = TSW-103-07-G-S: Header, 100mil, 3x1, Gold, TH; Manufacturer: Samtec; SymbolCreator: a0799628; U/M: EA
J9 J10 J12 = TSW-102-07-G-S: Header, 100mil, 2x1, Gold, TH; Manufacturer: Samtec; SymbolCreator: a0412235; Pitch_mm: 2.54; Gender: Male; Shrouded: N; Row_Count: 1; Current_A: 6.3; Voltage_V: 550; Cert_CSA: Y
J11 = TSW-104-07-G-S: Header, 100mil, 4x1, Gold, TH; Manufacturer: Samtec; SymbolCreator: a0412235; Pitch_mm: 2.54; Gender: Male; Shrouded: N; Row_Count: 1; Current_A: 6.3; Voltage_V: 550; Cert_CSA: Y; Green_Lifecycle: Active; Green_REACh: Passed
R22 R27 R31 = CRCW04021K00FKED: RES, 1.00 k, 1%, 0.063 W, 0402; Manufacturer: Vishay-Dale; CompType: Resistor; Value: 1.00k; Res_ohm: 1000; Value_Code: 1k00; Tolerance_%: 1; Power_W: 0.063; Value2: 0.063W; VDC_V: 50; TempCo: 100 ppm/C; SizeArea_mm2: 0.5; SizeZ_mm: 0.6; EIA_Code: E96; U/M: EA; AEC Category: Q200
R23 R26 R30 R35 R36 R39 R40 R42 R45 = CRCW040210K0FKED: as R3 on sheet PMP15043-1
R24 = RC0603FR-07499RL: RES, 499, 1%, 0.1 W, 0603; Manufacturer: Yageo America; CompType: Resistor; Value: 499; Value_Code: 499R; Tolerance_%: 1; Power_W: 0.1; Value2: 0.1W; VDC_V: 150; TempCo: 200 ppm/C; SizeArea_mm2: 1.28; SizeX_mm: 1.6; SizeY_mm: 0.8; EIA_Code: E96; U/M: EA; AEC Category: Q200; Green_Lifecycle: Active; Green_REACh: Passed
R25 R34 = CRCW04024K02FKED: RES, 4.02 k, 1%, 0.063 W, 0402; Manufacturer: Vishay-Dale; CompType: Resistor; Value: 4.02k; Res_ohm: 4020; Value_Code: 4k02; Tolerance_%: 1; Power_W: 0.063; Value2: 0.063W; VDC_V: 50; TempCo: 100 ppm/C; SizeArea_mm2: 0.5; SizeZ_mm: 0.6; EIA_Code: E96; U/M: EA; AEC Category: Q200; Green_Lifecycle: Active; Green_REACh: Passed
R28 R37 = CRCW0402100RFKED: RES, 100, 1%, 0.063 W, 0402; Manufacturer: Vishay-Dale; CompType: Resistor; Value: 100; Value_Code: 100R; Tolerance_%: 1; Power_W: 0.063; Value2: 0.063W; VDC_V: 50; TempCo: 100 ppm/C; SizeArea_mm2: 0.5; SizeZ_mm: 0.6; EIA_Code: E96; U/M: EA; AEC Category: Q200; Green_Lifecycle: Active; Green_REACh: Passed
R29 R32 R33 R38 = CRCW040251K1FKED: RES, 51.1 k, 1%, 0.063 W, 0402; Manufacturer: Vishay-Dale; CompType: Resistor; Value: 51.1k; Res_ohm: 51100; Value_Code: 51k1; Tolerance_%: 1; Power_W: 0.063; Value2: 0.063W; VDC_V: 50; TempCo: 100 ppm/C; SizeArea_mm2: 0.5; SizeZ_mm: 0.6; EIA_Code: E96; U/M: EA; AEC Category: Q200; Green_Lifecycle: Active; Green_REACh: Passed
R41 = CRCW040269K8FKED: RES, 69.8 k, 1%, 0.063 W, 0402; Manufacturer: Vishay-Dale; CompType: Resistor; Value: 69.8k; Res_ohm: 69800; Value_Code: 69k8; Tolerance_%: 1; Power_W: 0.063; Value2: 0.063W; VDC_V: 50; TempCo: 100 ppm/C; SizeArea_mm2: 0.5; SizeZ_mm: 0.6; EIA_Code: E96; U/M: EA; AEC Category: Q200; Green_Lifecycle: Active; Green_REACh: Passed
R43 = CRCW040290K9FKED: RES, 90.9 k, 1%, 0.063 W, 0402; Manufacturer: Vishay-Dale; CompType: Resistor; Value: 90.9k; Res_ohm: 90900; Value_Code: 90k9; Tolerance_%: 1; Power_W: 0.063; Value2: 0.063W; VDC_V: 50; TempCo: 100 ppm/C; SizeArea_mm2: 0.5; SizeZ_mm: 0.6; EIA_Code: E96; U/M: EA; AEC Category: Q200; Green_Lifecycle: Active; Green_REACh: Passed
R44 = CRCW040242K2FKED: RES, 42.2 k, 1%, 0.063 W, 0402; Manufacturer: Vishay-Dale; CompType: Resistor; Value: 42.2k; Res_ohm: 42200; Value_Code: 42k2; Tolerance_%: 1; Power_W: 0.063; Value2: 0.063W; VDC_V: 50; TempCo: 100 ppm/C; SizeArea_mm2: 0.5; SizeZ_mm: 0.6; EIA_Code: E96; U/M: EA; AEC Category: Q200
R46 = CRCW040230K1FKED: RES, 30.1 k, 1%, 0.063 W, 0402; Manufacturer: Vishay-Dale; CompType: Resistor; Value: 30.1k; Res_ohm: 30100; Value_Code: 30k1; Tolerance_%: 1; Power_W: 0.063; Value2: 0.063W; VDC_V: 50; TempCo: 100 ppm/C; SizeArea_mm2: 0.5; SizeZ_mm: 0.6; EIA_Code: E96; U/M: EA; AEC Category: Q200; Green_Lifecycle: Active; Green_REACh: Passed
U6 = INA188IDR: 36-V, Zero-Drift, Rail-to-Rail-Out Instrumentation Amplifier, D0008A (SOIC-8); Manufacturer: Texas Instruments; SymbolCreator: a0411947; SizeArea_mm2: 30.38; SizeAreaWB_mm2: 56.58; SizeX_mm: 4.9; SizeY_mm: 6.2; SizeZ_mm: 1.75; CompType: IC; U/M: EA
U7-U10 = OP07CD: Low-Offset Voltage Operational Amplifier, 6 to 36 V, 0 to 70 degC, 8-pin SOIC (D0008A), Green (RoHS & no Sb/Br); Alternate Manufacturer: Texas Instruments; Alternate PartNumber: Equivalent; CMRR(Min)(dB): 100; GBW(Typ)(MHz): 0.6; IIB(Max)(pA): 7000; Iq per channel(Max)(mA): 5; Number of Channels: 1; Offset Drift(Typ)(uV/C): 0.5; Rating: Catalog; Slew Rate(Typ)(V/us): 0.3; Sub Family: General Purpose Amplifier, High Supply Voltage Amplifier (>=30V), Low Noise Amp (<=10nV/rtHz), Low Offset Voltage Amplifier (<=500uV); Total Supply Voltage(Max)(+5V is 5, +/-5V is 10): 36; Total Supply Voltage(Min)(+5V is 5, +/-5V is 10): 6; Vio (25C)(Max)(mV): 0.15; Vn at 1kHz(Typ)(nV/rtHz): 9.8

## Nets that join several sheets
+5V: PMP15043-1 (9 pins), PMP15043-2 (9 pins)
-5V: PMP15043-1 (C19.1 U5.2), PMP15043-2 (8 pins)
COMP_BOOST: PMP15043-1 (R10.2 U1.4), PMP15043-2 (C24.1 D4.1 R25.1)
GND: PMP15043-1 (44 pins), PMP15043-2 (24 pins)
+9V: PMP15043-1 (C40.1 U11.1), PMP15043-2 (C21.1 U6.7 U8.7 U10.7)
BST_EN: PMP15043-1 (R3.2 R14.1 U1.11), PMP15043-2 (J11.3)
BUCK_EN: PMP15043-1 (R19.1 R47.1), PMP15043-2 (J11.2)
COMP_BUCK: PMP15043-1 (U4.8), PMP15043-2 (C32.1 D6.1 R34.1)
ISEN+: PMP15043-1 (U2.1 U2.12), PMP15043-2 (C25.1 U6.3)
ISEN-: PMP15043-1 (U2.2 U2.13), PMP15043-2 (C23.1 U6.2)
VIN: PMP15043-1 (8 pins), PMP15043-2 (R37.1)

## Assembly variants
001: not fitted FID1 FID2 FID3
